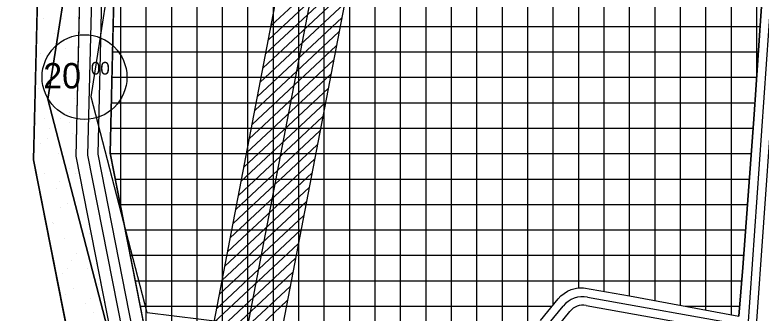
# Model space of a CAD drawing. Extents: x 419109 to 421295, y 4452223 to 4457798.
# Drawn here: x 419759.2 to 420199.2, y 4455197.7 to 4455373.6 of the extents above; entities that cross this region are included whole.
import ezdxf

# ---------------------------------------------------------------- set-up
doc = ezdxf.new("R2010")
doc.units = 0
for name, color, linetype in [('ADAKENARI', 7, 'Continuous'), ('KALDIRIM_FAT', 7, 'Continuous'), ('KD_DAIRE', 7, 'Continuous'), ('KD_YGEN', 7, 'Continuous'), ('PL_AYA_PARK_DINLENME', 7, 'Continuous'), ('PL_KA_TARIM_ALANI', 7, 'Continuous'), ('PL_TİCARET', 7, 'Continuous'), ('TA_ENH_154', 7, 'Continuous'), ('TA_ENH_KORUMA', 7, 'Continuous'), ('TA_ENH_TARAMA', 7, 'Continuous'), ('TRFAT_PARKALANI', 7, 'Continuous'), ('TRFAT_TİCARET', 7, 'Continuous')]:
    doc.layers.add(name, color=color, linetype=linetype)

msp = doc.modelspace()

# ---------------------------------------------------------------- linework, layer by layer
at = {"layer": 'ADAKENARI'}
for p, q in [((419770.22, 4455288.15), (419772.93, 4455400.8)), ((420200.5, 4455392.26), (420199.15, 4455373.07)), ((419795.28, 4455290.29), (419797.57, 4455385.64)), ((419815.33, 4455292.01), (419817.56, 4455384.81)), ((420199.15, 4455373.07), (420195.2, 4455314.87)), ((420195.2, 4455314.87), (420188.54, 4455224.54)), ((419836.87, 4455182.74), (419815.33, 4455292.01)), ((419798.46, 4455144.95), (419770.22, 4455288.15)), ((419822.71, 4455151.21), (419795.28, 4455290.29)), ((420188.54, 4455224.54), (420186.09, 4455195.96)), ((420081.21, 4455207.82), (420083.07, 4455209.33)), ((420083.07, 4455209.33), (420085.11, 4455210.59)), ((420085.11, 4455210.59), (420087.3, 4455211.56)), ((420087.3, 4455211.56), (420089.6, 4455212.24)), ((420089.6, 4455212.24), (420090.3, 4455212.34)), ((420090.3, 4455212.34), (420091.97, 4455212.6)), ((420091.97, 4455212.6), (420094.58, 4455212.63)), ((420094.58, 4455212.63), (420121.64, 4455207.8)), ((420069.08, 4455193.26), (420079.57, 4455206.07)), ((420079.57, 4455206.07), (420081.21, 4455207.82)), ((420121.64, 4455207.8), (420186.09, 4455195.96))]:
    msp.add_line(p, q, dxfattribs=at)
at = {"layer": 'KALDIRIM_FAT'}
for p, q in [((420215.94, 4455540.77), (420179.4, 4455019.05)), ((420220.93, 4455540.45), (420184.39, 4455018.74)), ((419802.3, 4455290.89), (419804.97, 4455402.08)), ((419808.31, 4455291.41), (419810.98, 4455402.32)), ((419830.51, 4455147.82), (419802.3, 4455290.89)), ((419836.23, 4455149.81), (419808.31, 4455291.41)), ((420096.91, 4455207.13), (420191.39, 4455190.25)), ((420071.54, 4455188.37), (420082.57, 4455201.84)), ((420096.03, 4455202.21), (420191.04, 4455185.24)), ((420075.41, 4455185.2), (420086.44, 4455198.67))]:
    msp.add_line(p, q, dxfattribs=at)
for radius in [15.11, 10.11]:
    msp.add_arc((420094.25, 4455192.26), radius, 79.8697, 140.6835, dxfattribs=at)
at = {"layer": 'KD_DAIRE'}
msp.add_circle((419800.27, 4455336.9), 25, dxfattribs=at)
at = {"layer": 'PL_AYA_PARK_DINLENME'}
for points in [[(419804.4, 4455678.61), (419776.71, 4455623), (419768.21, 4455605.99), (419766.74, 4455602.8), (419765.22, 4455598.83), (419763.96, 4455594.76), (419762.97, 4455590.63), (419762.84, 4455589.82), (419762.4, 4455587.24), (419762.26, 4455586.44), (419761.82, 4455582.21), (419761.65, 4455577.95), (419761.75, 4455574.44), (419762.54, 4455561.28), (419771.07, 4455418.55), (419772.93, 4455400.8), (419770.22, 4455288.15), (419798.46, 4455144.95), (419791.07, 4455126.52), (419788.42, 4455109.34), (419786.36, 4455074.3), (419779.83, 4455031.69), (419779.71, 4455015.11)], [(419794.56, 4455425.51), (419778.68, 4455323.91), (419819.96, 4455165.16), (419792.54, 4455014.98)], [(419884.24, 4455014.01), (419916.83, 4455187.99), (419837.29, 4455197.86), (419804.18, 4455325.18), (419819.77, 4455424.95)], [(419804.71, 4455014.85), (419804.81, 4455029.69), (419811.24, 4455071.67), (419813.3, 4455106.69), (419815.34, 4455119.87), (419824.84, 4455143.55), (419823.83, 4455145.49), (419822.71, 4455151.21), (419795.28, 4455290.29), (419797.57, 4455385.64)]]:
    msp.add_lwpolyline(points, dxfattribs=at)
at = {"layer": 'PL_KA_TARIM_ALANI'}
msp.add_lwpolyline([(419792.54, 4455014.98), (419819.96, 4455165.16), (419778.68, 4455323.91), (419794.56, 4455425.51), (419783.44, 4455525.52), (419756.46, 4455592.19), (419823.13, 4455660.45), (419824.72, 4455719.19), (419900.92, 4456001.76), (419869.84, 4456009.19), (419715.18, 4456046.21), (419743.76, 4456181.14), (419781.86, 4456219.24), (419851.71, 4456390.68), (419896.15, 4456444.66), (419972.35, 4456528.79), (420021.56, 4456763.74), (420013.63, 4456854.22), (420016.8, 4456927.25), (420027.91, 4457006.62), (420158.52, 4456994.43), (420142.12, 4457086.4)], dxfattribs=at)
at = {"layer": 'PL_TİCARET'}
for points in [[(420069.08, 4455193.26), (420079.57, 4455206.07), (420081.21, 4455207.82), (420083.07, 4455209.33), (420085.11, 4455210.59), (420087.3, 4455211.56), (420089.6, 4455212.24), (420090.3, 4455212.34), (420091.97, 4455212.6), (420094.58, 4455212.63), (420121.64, 4455207.8), (420186.09, 4455195.96), (420188.54, 4455224.54), (420188.54, 4455224.54), (420195.2, 4455314.87), (420199.15, 4455373.07), (420200.5, 4455392.26)], [(419817.56, 4455384.81), (419815.33, 4455292.01), (419836.87, 4455182.74)]]:
    msp.add_lwpolyline(points, dxfattribs=at)
at = {"layer": 'TA_ENH_154'}
msp.add_lwpolyline([(419862.83, 4455014.24), (420170.14, 4456613.6), (420230.68, 4456928.68), (420176.89, 4457440.84), (420133.44, 4457787.81)], dxfattribs=at)
at = {"layer": 'TA_ENH_KORUMA'}
msp.add_line((419842.5, 4455014.45), (420150.5, 4456617.38), dxfattribs=at)
msp.add_lwpolyline([(420153.62, 4457787.6), (420196.76, 4457443.12), (420250.88, 4456927.82), (420189.78, 4456609.83), (419883.15, 4455014.02)], dxfattribs=at)
at = {"layer": 'TA_ENH_TARAMA'}
for p, q in [((419910.29, 4455367.25), (419959.94, 4455413.65)), ((419908.68, 4455358.91), (419958.34, 4455405.31)), ((419907.08, 4455350.57), (419956.73, 4455396.97)), ((419905.48, 4455342.23), (419955.13, 4455388.63)), ((419903.88, 4455333.88), (419953.53, 4455380.29)), ((419902.27, 4455325.54), (419951.92, 4455371.94)), ((419900.67, 4455317.2), (419950.32, 4455363.6)), ((419899.07, 4455308.86), (419948.72, 4455355.26)), ((419897.46, 4455300.52), (419947.12, 4455346.92)), ((419895.86, 4455292.17), (419945.51, 4455338.57)), ((419894.26, 4455283.83), (419943.91, 4455330.23)), ((419892.66, 4455275.49), (419942.31, 4455321.89)), ((419891.05, 4455267.15), (419940.7, 4455313.55)), ((419889.45, 4455258.8), (419939.1, 4455305.21)), ((419887.85, 4455250.46), (419937.5, 4455296.86)), ((419886.24, 4455242.12), (419935.9, 4455288.52)), ((419884.64, 4455233.78), (419934.29, 4455280.18)), ((419883.04, 4455225.44), (419932.69, 4455271.84)), ((419881.44, 4455217.09), (419931.09, 4455263.49)), ((419879.83, 4455208.75), (419929.48, 4455255.15)), ((419878.23, 4455200.41), (419927.88, 4455246.81)), ((419876.63, 4455192.07), (419926.28, 4455238.47)), ((419875.02, 4455183.72), (419924.67, 4455230.13)), ((419873.42, 4455175.38), (419923.07, 4455221.78)), ((419871.82, 4455167.04), (419921.47, 4455213.44)), ((419870.21, 4455158.7), (419919.87, 4455205.1))]:
    msp.add_line(p, q, dxfattribs=at)
at = {"layer": 'TRFAT_PARKALANI'}
for p, q in [((419775.97, 4455371.51), (419775.97, 4455371.51)), ((419787.22, 4455371.62), (419787.22, 4455371.62)), ((419796.13, 4455372.49), (419796.13, 4455372.49)), ((419782.63, 4455362.53), (419782.63, 4455362.53)), ((419784.64, 4455362.85), (419784.64, 4455362.85)), ((419784.62, 4455356.85), (419784.62, 4455356.85)), ((419774.52, 4455350.94), (419774.52, 4455350.94)), ((419789.29, 4455353.55), (419789.29, 4455353.55)), ((419775.75, 4455342.33), (419775.75, 4455342.33)), ((419781.18, 4455341.96), (419781.18, 4455341.96)), ((419795.95, 4455344.57), (419795.95, 4455344.57)), ((419780.28, 4455332.23), (419780.28, 4455332.23)), ((419787.84, 4455332.98), (419787.84, 4455332.98)), ((419795.92, 4455334.55), (419795.92, 4455334.55)), ((419773.07, 4455330.38), (419773.07, 4455330.38)), ((419794.5, 4455324), (419794.5, 4455324)), ((419779.73, 4455321.4), (419779.73, 4455321.4)), ((419791.2, 4455316.13), (419791.2, 4455316.13)), ((419771.62, 4455309.81), (419771.62, 4455309.81)), ((419776.81, 4455312.54), (419776.81, 4455312.54)), ((419786.39, 4455312.42), (419786.39, 4455312.42)), ((419791.58, 4455309.93), (419791.58, 4455309.93)), ((419779.71, 4455306.49), (419779.71, 4455306.49)), ((419778.28, 4455300.83), (419778.28, 4455300.83)), ((419793.05, 4455303.44), (419793.05, 4455303.44)), ((419774.2, 4455297.76), (419774.2, 4455297.76)), ((419784.94, 4455291.85), (419784.94, 4455291.85)), ((419788.1, 4455290.23), (419788.1, 4455290.23)), ((419770.82, 4455285.98), (419770.82, 4455285.98)), ((419776.83, 4455280.27), (419776.83, 4455280.27)), ((419791.6, 4455282.87), (419791.6, 4455282.87)), ((419795.17, 4455280.3), (419795.17, 4455280.3)), ((419785.5, 4455275.46), (419785.5, 4455275.46)), ((419783.49, 4455271.29), (419783.49, 4455271.29)), ((419798.26, 4455273.89), (419798.26, 4455273.89)), ((419799.4, 4455267.93), (419799.4, 4455267.93)), ((419790.15, 4455262.31), (419790.15, 4455262.31)), ((419786.27, 4455259.78), (419786.27, 4455259.78)), ((419796.8, 4455253.16), (419796.8, 4455253.16)), ((419796.81, 4455253.33), (419796.81, 4455253.33)), ((419781.16, 4455250.84), (419781.16, 4455250.84)), ((419782.04, 4455250.72), (419782.04, 4455250.72)), ((419803.47, 4455244.35), (419803.47, 4455244.35)), ((419788.7, 4455241.74), (419788.7, 4455241.74)), ((419795.36, 4455232.76), (419795.36, 4455232.76)), ((419801.73, 4455233.59), (419801.73, 4455233.59)), ((419792.46, 4455228.54), (419792.46, 4455228.54)), ((419790.24, 4455223.94), (419790.24, 4455223.94)), ((419802.02, 4455223.78), (419802.02, 4455223.78)), ((419787.24, 4455221.18), (419787.24, 4455221.18)), ((419808.68, 4455214.8), (419808.68, 4455214.8)), ((419788.98, 4455208.85), (419788.98, 4455208.85)), ((419793.91, 4455212.2), (419793.91, 4455212.2)), ((419803.76, 4455206.24), (419803.76, 4455206.24)), ((419800.57, 4455203.22), (419800.57, 4455203.22)), ((419805.69, 4455197.75), (419805.69, 4455197.75))]:
    msp.add_line(p, q, dxfattribs=at)
at = {"layer": 'TRFAT_TİCARET'}
for p, q in [((420166.68, 4455199.52), (420166.68, 4456009.42)), ((420151.68, 4455202.28), (420151.68, 4455965.68)), ((420136.68, 4455205.03), (420136.68, 4455929.15)), ((420121.68, 4455207.79), (420121.68, 4455897.66)), ((420076.68, 4455202.54), (420076.68, 4455803.79)), ((420061.68, 4455185.7), (420061.68, 4455772.5)), ((420046.68, 4455173.41), (420046.68, 4455741.21)), ((420031.68, 4455161.13), (420031.68, 4455713.07)), ((420016.68, 4455148.86), (420016.68, 4455685.9)), ((420001.68, 4455136.59), (420001.68, 4455658.72)), ((419986.68, 4455124.32), (419986.68, 4455631.54)), ((419821.68, 4455259.79), (419821.68, 4455609.31)), ((419836.68, 4455183.73), (419836.68, 4455606.37)), ((419851.68, 4455183.32), (419851.68, 4455600.16)), ((419971.68, 4455112.05), (419971.68, 4455604.36)), ((419866.68, 4455183.91), (419866.68, 4455594.51)), ((420091.68, 4455212.55), (420091.68, 4455591.43)), ((420106.68, 4455210.47), (420106.68, 4455591.43)), ((419881.68, 4455184.49), (419881.68, 4455589.42)), ((419896.68, 4455185.08), (419896.68, 4455582.37)), ((419911.68, 4455175.86), (419911.68, 4455574.55)), ((419956.68, 4455127.52), (419956.68, 4455577.19)), ((419926.68, 4455159.75), (419926.68, 4455566.73)), ((419941.68, 4455143.64), (419941.68, 4455558.89)), ((420181.68, 4455196.77), (420181.68, 4455506.05)), ((420196.68, 4455336.59), (420196.68, 4455500.33)), ((419817.12, 4455366.77), (420198.73, 4455366.77)), ((419816.76, 4455351.77), (420197.71, 4455351.77)), ((419816.4, 4455336.77), (420196.69, 4455336.77)), ((419816.04, 4455321.77), (420195.67, 4455321.77)), ((419815.68, 4455306.77), (420194.61, 4455306.77)), ((419815.37, 4455291.77), (420193.5, 4455291.77)), ((419818.33, 4455276.77), (420192.39, 4455276.77)), ((419821.29, 4455261.77), (420191.29, 4455261.77)), ((419824.25, 4455246.77), (420190.18, 4455246.77)), ((419827.2, 4455231.77), (420189.07, 4455231.77)), ((419830.16, 4455216.77), (420187.87, 4455216.77)), ((419833.12, 4455201.77), (420076.05, 4455201.77)), ((420154.43, 4455201.77), (420186.58, 4455201.77))]:
    msp.add_line(p, q, dxfattribs=at)

# ---------------------------------------------------------------- texts
at = {"layer": 'KD_YGEN'}
for s, height, p in [('20', 15, (419775.92, 4455330.2)), ('00', 7.5, (419804.01, 4455338.36))]:
    msp.add_text(s, height=height, dxfattribs=at).set_placement(p)

doc.saveas('drawing.dxf')
